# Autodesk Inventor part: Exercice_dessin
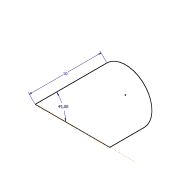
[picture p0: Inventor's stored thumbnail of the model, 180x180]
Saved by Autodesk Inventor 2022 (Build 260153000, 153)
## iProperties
Created: 2021-05
Part Number: Exercice_dessin
Material: Générique
Document SubType Name: Modeling
Designer: Fabian
Density: 1 g/cm^3
Appearance: Par défaut
Author: Fabian
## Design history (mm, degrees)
sketch "Esquisse1"
  geometry: L1 (0, 0)-(7.071, 7.071); L2 (0, 0)-(10, 0); L3 (10.747, 3.395)-(7.352, 0); L4 (7.352, 0)-(0, 0); A1 r 2.599 centre (8.909, 5.233) between (10.747, 3.395) and (7.071, 7.071)
  constraints: 8 end point, 2 horizontal, 2 point on circle, 2 tangent, 1 centre point, 1 equal length, 1 parallel
  dimensions: "d26" = 10 dimension on L1.start L1.end L1 L2.end L2 L3.start A1.centre A1 L3.end L3 L4; "d26" = 10 distance of L1.start L1.end; "d27" = 45 deg angle of L2 L1
node "Solide1"
